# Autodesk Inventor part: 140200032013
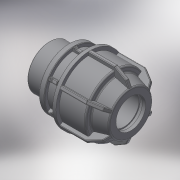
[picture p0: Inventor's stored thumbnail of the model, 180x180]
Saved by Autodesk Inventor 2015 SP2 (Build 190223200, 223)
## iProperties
Created: 2017-08
Part Number: 140200032013
Material: Generic
Description: PLASSON L.14 MALE ADAPTOR (SILVER) 32-1.1/4''
Document SubType Name: Modeling
Designer: KIM
Density: 1 g/cm^3
Appearance: Default
Author: KIM
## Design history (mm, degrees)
derived "140200.ipt"
feature "Solid1::140200.ipt"
tag "TaggingFeature1"
body "Solid1"
other parameters: "d1" = 32, "d2" = 58, "d4" = 15 deg, "d5" = 38.28, "d6" = 12.6324, "d10" = 61, "d16" = 32.64, "d17" = 2.9, "d18" = 86, "d19" = 6, "d21" = 6, "d22" = 50.292, "d24" = 2.9, "d25" = 54.9, "d26" = 45.75, "d27" = 2.9, "d28" = 135 deg, "d29" = 1.74, "d31" = 1.6, "d44" = 0.64, "d45" = 0.96, "d46" = 150 deg, "d49" = 3.05, "d50" = 0, "d51" = 1.83, "d52" = 1.22, "d53" = 45 deg, "d54" = 21, "d55" = 8.4, "d56" = 3.05, "d57" = 0, "d58" = 0.96, "d59" = 0.64, "d61" = 360 deg, "d63" = 41.91, "d64" = 25.6, "d66" = 56.5785, "d_" = 32, "R_" = 41.91, "E_" = 61, "H_" = 86, "l_" = 58
